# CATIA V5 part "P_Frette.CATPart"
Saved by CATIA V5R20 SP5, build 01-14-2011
Part number: Frette
Bounding box of the stored display mesh (mm): x -111.136 to 111.136, y 187.776 to 409.951, z -10 to 150
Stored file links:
  U:\2A\CFAO\dossier sans titre\P_Frette.CATPart
  U:\2A\CFAO\dossier sans titre\Gouvernail.CATProduct
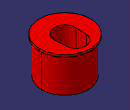
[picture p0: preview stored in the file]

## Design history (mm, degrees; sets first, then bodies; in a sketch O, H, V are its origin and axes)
External parameters (linked from other documents)
  External.Larg_Totale = 450 mm
Set1
  Point1: linked copy from another document
  Point2: linked copy from another document
  Point3 "Point.23": linked copy from another document
  Point4: linked copy from another document
  Point5 "Point.24": linked copy from another document
  Point6: linked copy from another document
Body1 (main body)
  Sketch1 on xy-plane, origin (0, 0, 0), H (1, 0, 0), V (0, 1, 0)
    axis line L1 (0, 491.5816) -> (0, -18.2853)
    construction arc A1 centre (0, 415) radius 35 from (-34.4998, 420.8959) to (34.4998, 420.8959) cw
    point P3 (0, 415)
    construction arc A2 centre (-803.3534, 277.7108) radius 850 from (34.4998, 420.8959) to (0, 0) cw
    construction arc A3 centre (803.3534, 277.7108) radius 850 from (-34.4998, 420.8959) to (0, 0) ccw
    reference projected point E1 (0, 450) from Point1
    arc A4 centre (0, 346.2739) radius 43.7261 from (-43.5677, 349.9922) to (43.5677, 349.9922) cw
    point P8 (0, 346.2739)
    point P9 (-43.5677, 349.9922)
    point P10 (43.5677, 349.9922)
    reference projected point E2 (0, 390) from Point2
    arc A5 centre (0, 298.8638) radius 46.3682 from (-46.3521, 300.0843) to (46.3521, 300.0843) ccw
    point P11 (0, 298.8638)
    point P12 (-46.3521, 300.0843)
    point P13 (46.3521, 300.0843)
    point P14 (-46.3521, 300.0843)
    arc A6 centre (803.3534, 277.7108) radius 850 from (-43.5677, 349.9922) to (-46.3521, 300.0843) ccw
    point P16 (-46.3521, 300.0843)
    arc A7 centre (-803.3534, 277.7108) radius 850 from (43.5677, 349.9922) to (46.3521, 300.0843) cw
    reference projected point E3 (0, 298.8638) from Point3
    circle A8 centre (0, 298.8638) radius 111.1365
    point P18 (0, 298.8638)
    reference projected point E4 (0, 298.8638) from Point3
    reference projected point E5 (0, 187.7273) from Point4
    radius A2 = 850 {= (850/450)*External.Larg_Totale}
    radius A3 = 850 {= (850/450)*External.Larg_Totale}
    radius A1 = 35 {= (35/450)*External.Larg_Totale}
    coincidence: L1 V, P3 L1, E1 A1, P9 A3, P10 A2, A4 E2, P8 L1, P12 A3, P13 A2, P14 A5, P14 A3, P16 A5, P16 A3, A6 A3, A7 A2, P11 E3, P18 E4, A8 E5, P12 P16
    tangency: A2 A1, A3 A1, A4 A7, A5 A7
  Pad1: profile Sketch1, direction (0, 0, 1), length 150, opposite side length 10
  Sketch2 on xy-plane, origin (0, 0, 0), H (1, 0, 0), V (0, 1, 0)
    circle A1 centre (0, 298.8638) radius 101.1365
    point P1 (0, 298.8638)
    reference projected point E1 (0, 298.8638) from Point5
    circle A2 centre (0, 298.8638) radius 111.1365
    point P2 (0, 298.8638)
    reference projected point E2 (0, 298.8638) from Point5
    reference projected point E3 (0, 187.7273) from Point6
    distance A1 A2 = 10
    coincidence: P1 E1, P2 E2, E3 A2
  Pocket1: profile Sketch2, direction (0, 0, 1), length 140, opposite side length 10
